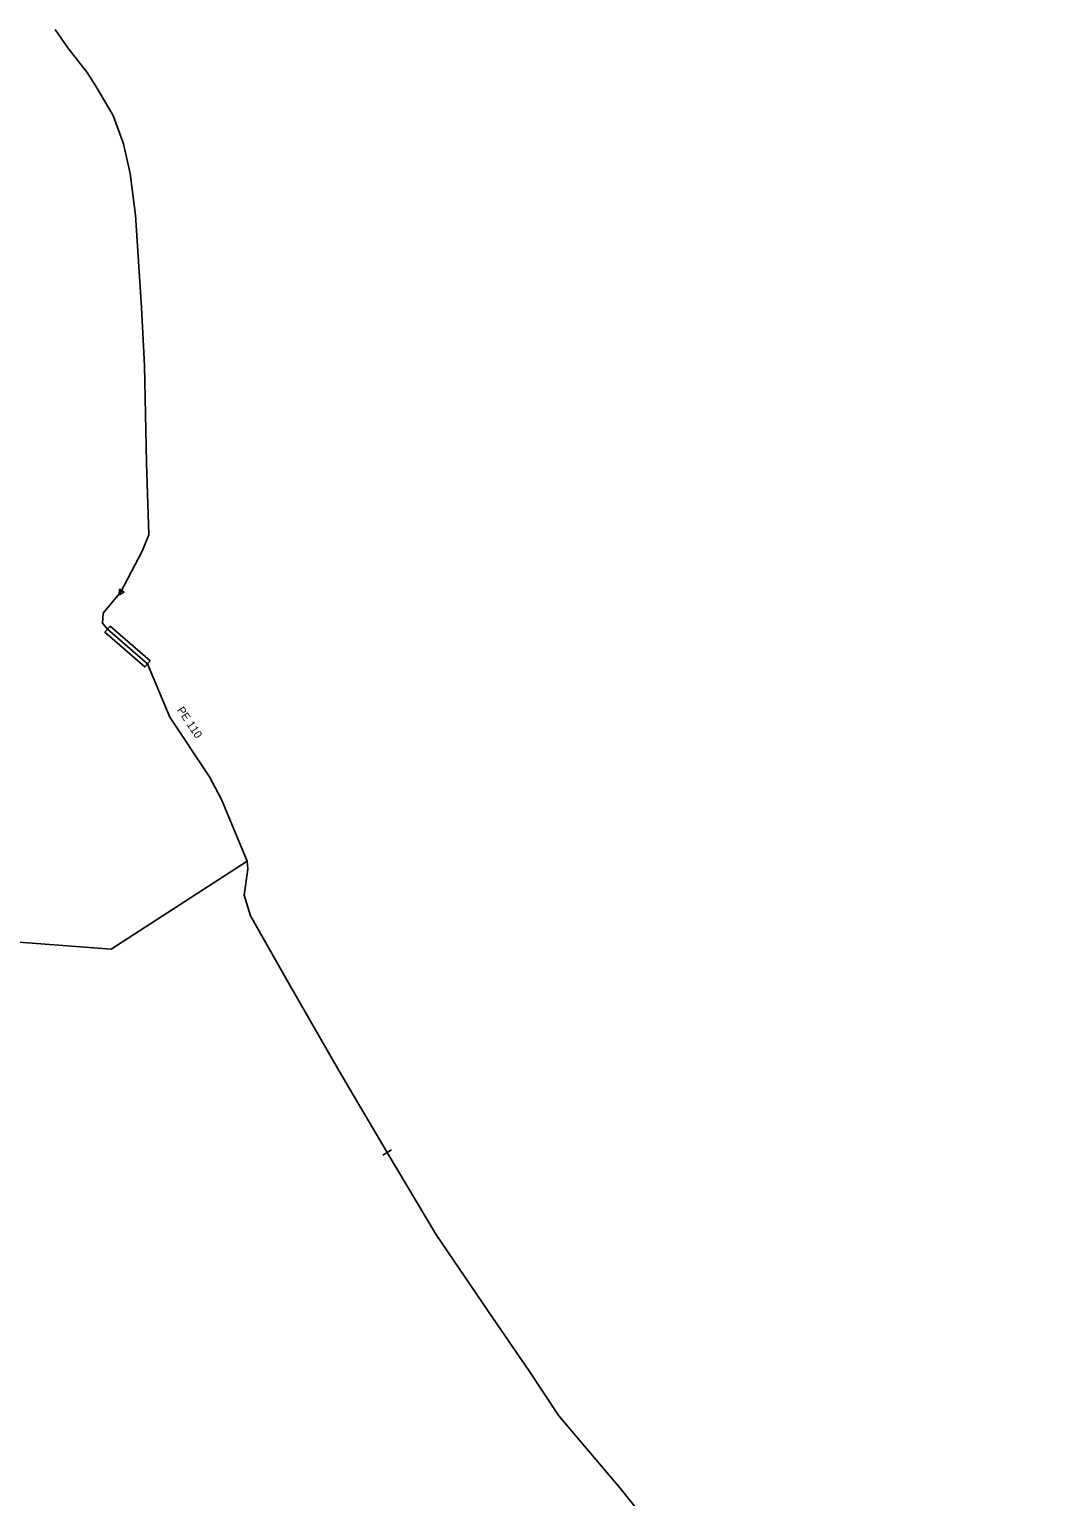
# Model space of a CAD drawing. Extents: x -867696 to -865033, y -1042522 to -1039817.
# Drawn here: x -865564.5 to -865310.4, y -1040312.7 to -1039946.1 of the extents above; entities that cross this region are included whole.
import ezdxf

# ---------------------------------------------------------------- set-up
doc = ezdxf.new("R2010")
doc.units = 0
for name, color, linetype in [('Level 1', 7, 'Continuous'), ('V - armatura', 7, 'Continuous'), ('V - ostatni', 7, 'Continuous'), ('V - popis material', 7, 'Continuous'), ('V - pripojka', 7, 'Continuous'), ('V - rozvadeci', 7, 'Continuous')]:
    doc.layers.add(name, color=color, linetype=linetype)

# ---------------------------------------------------------------- blocks, each defined once
blk = doc.blocks.new('111')
at = {"layer": 'Level 1'}
for p, q in [((0.42, 0.72), (-0.83, 0)), ((-0.83, 0), (0.42, -0.72)), ((0.42, -0.72), (0.42, 0.72))]:
    blk.add_line(p, q, dxfattribs=at)
blk = doc.blocks.new('147')
at = {"layer": 'Level 1'}
blk.add_line((0, 1.27), (0, -1.27), dxfattribs=at)

msp = doc.modelspace()

# ---------------------------------------------------------------- linework, layer by layer
at = {"layer": 'V - ostatni'}
msp.add_lwpolyline([(-865544.324, -1040095.165), (-865534.294, -1040103.875), (-865535.606, -1040105.385), (-865545.636, -1040096.675), (-865544.324, -1040095.165)], dxfattribs=at)
at = {"layer": 'V - pripojka'}
msp.add_lwpolyline([(-865510, -1040153.97), (-865544.067, -1040175.886), (-865572.682, -1040173.74), (-865649.227, -1040232.639), (-865708.365, -1040263.52), (-865813.049, -1040306.443)], dxfattribs=at)
at = {"layer": 'V - rozvadeci'}
for points in [[(-865558.01, -1039946.05), (-865554.88, -1039950.67), (-865550.04, -1039956.87), (-865547.9, -1039960.28), (-865543.53, -1039967.59), (-865540.98, -1039974.7), (-865539.27, -1039982.08), (-865537.98, -1039992.48), (-865536.47, -1040015.6), (-865535.67, -1040030.08), (-865535.22, -1040054.37), (-865534.62, -1040072.36), (-865536.3, -1040076.49), (-865541.61, -1040086.66)], [(-865475, -1040226.72), (-865487.15, -1040206.28), (-865499.7, -1040184.3), (-865509.2, -1040167.58), (-865510.82, -1040162.42), (-865509.87, -1040155.91), (-865510, -1040153.97), (-865516.44, -1040138.54), (-865519.42, -1040132.83), (-865529.4, -1040117.91), (-865534.95, -1040104.63), (-865544.98, -1040095.92), (-865546.19, -1040094.44), (-865546.05, -1040091.94), (-865541.61, -1040086.66)], [(-865310.4, -1040476.96), (-865313.82, -1040464.78), (-865318.3, -1040450.9), (-865322.26, -1040439.46), (-865331.99, -1040416.94), (-865336.6, -1040409.59), (-865353.57, -1040386.1), (-865370.65, -1040364.06), (-865377.64, -1040355.01), (-865391.52, -1040340.63), (-865403.28, -1040327.47), (-865416.82, -1040310.65), (-865432.1, -1040292.52), (-865439.48, -1040281.44), (-865449.81, -1040266.41), (-865462.85, -1040247.16), (-865475, -1040226.72)]]:
    msp.add_lwpolyline(points, dxfattribs=at)

# ---------------------------------------------------------------- block references
at = {"layer": 'V - armatura', "xscale": 1.0000000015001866, "yscale": 1.0000000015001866, "rotation": -59.00000017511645}
msp.add_blockref('147', (-865475, -1040226.72), dxfattribs=at)
at = {"layer": 'V - ostatni', "xscale": 0.9999999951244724, "yscale": 0.9999999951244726, "rotation": 56.999998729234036}
msp.add_blockref('111', (-865541.61, -1040086.66), dxfattribs=at)

# ---------------------------------------------------------------- texts
at = {"layer": 'V - popis material'}
msp.add_text('PE 110', height=2, rotation=303.78, dxfattribs=at).set_placement((-865527.67, -1040116.154))

doc.saveas('drawing.dxf')
